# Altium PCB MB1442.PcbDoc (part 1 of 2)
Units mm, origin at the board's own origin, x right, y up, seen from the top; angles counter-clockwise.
Board outline 18.54 x 50.29 mm, 4 copper layers (Top Layer, Signal Layer 1, Signal Layer 2, Bottom Layer); 93 components, 78 nets, 322 pads, 169 vias.
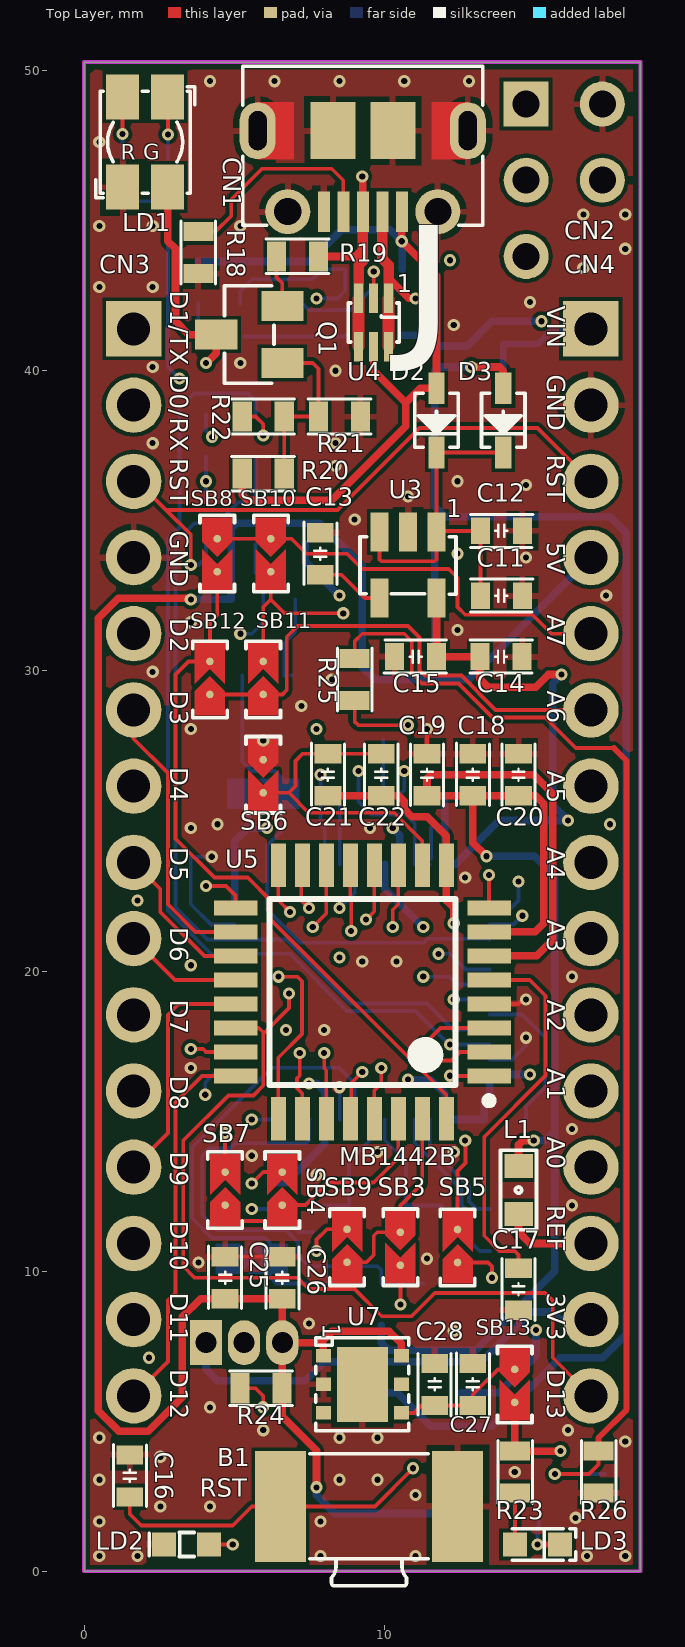
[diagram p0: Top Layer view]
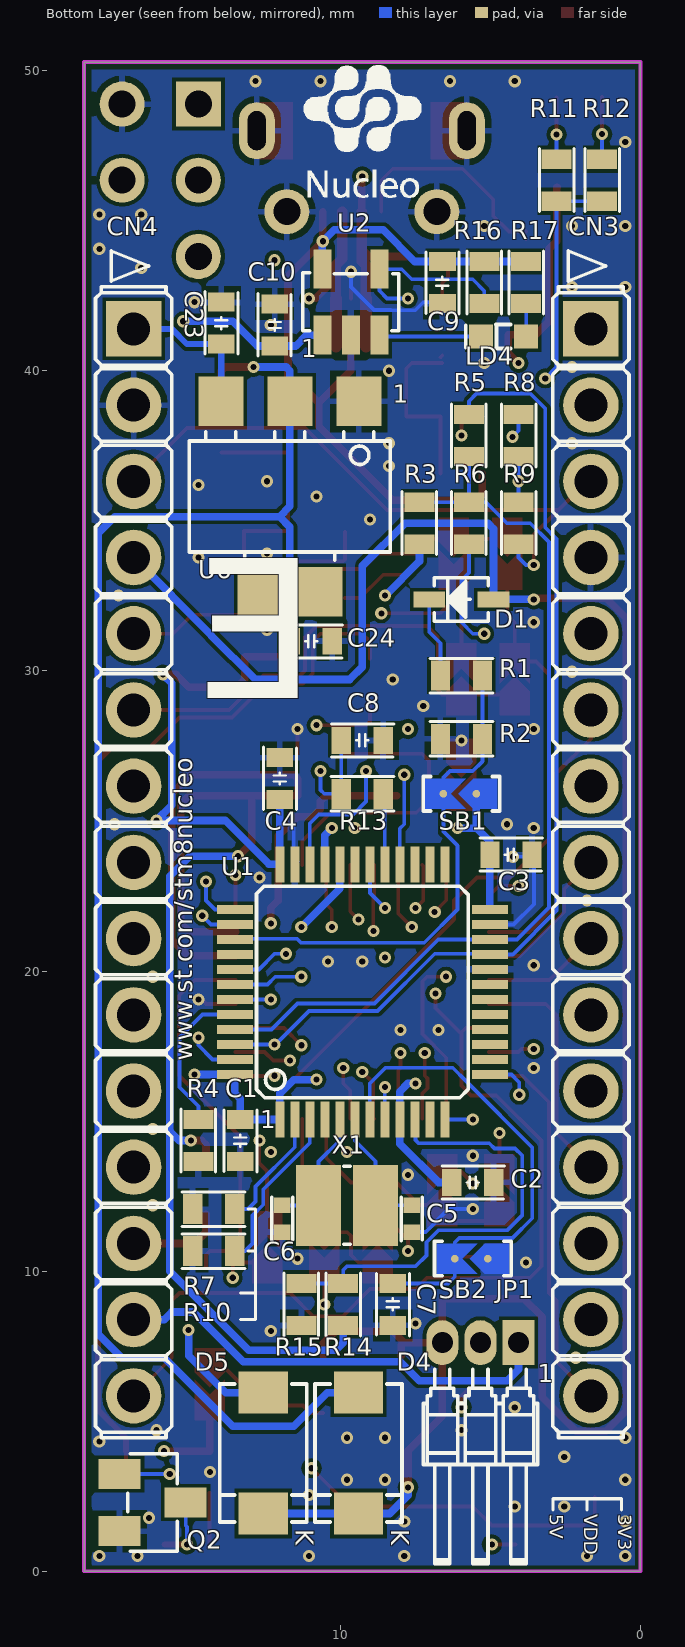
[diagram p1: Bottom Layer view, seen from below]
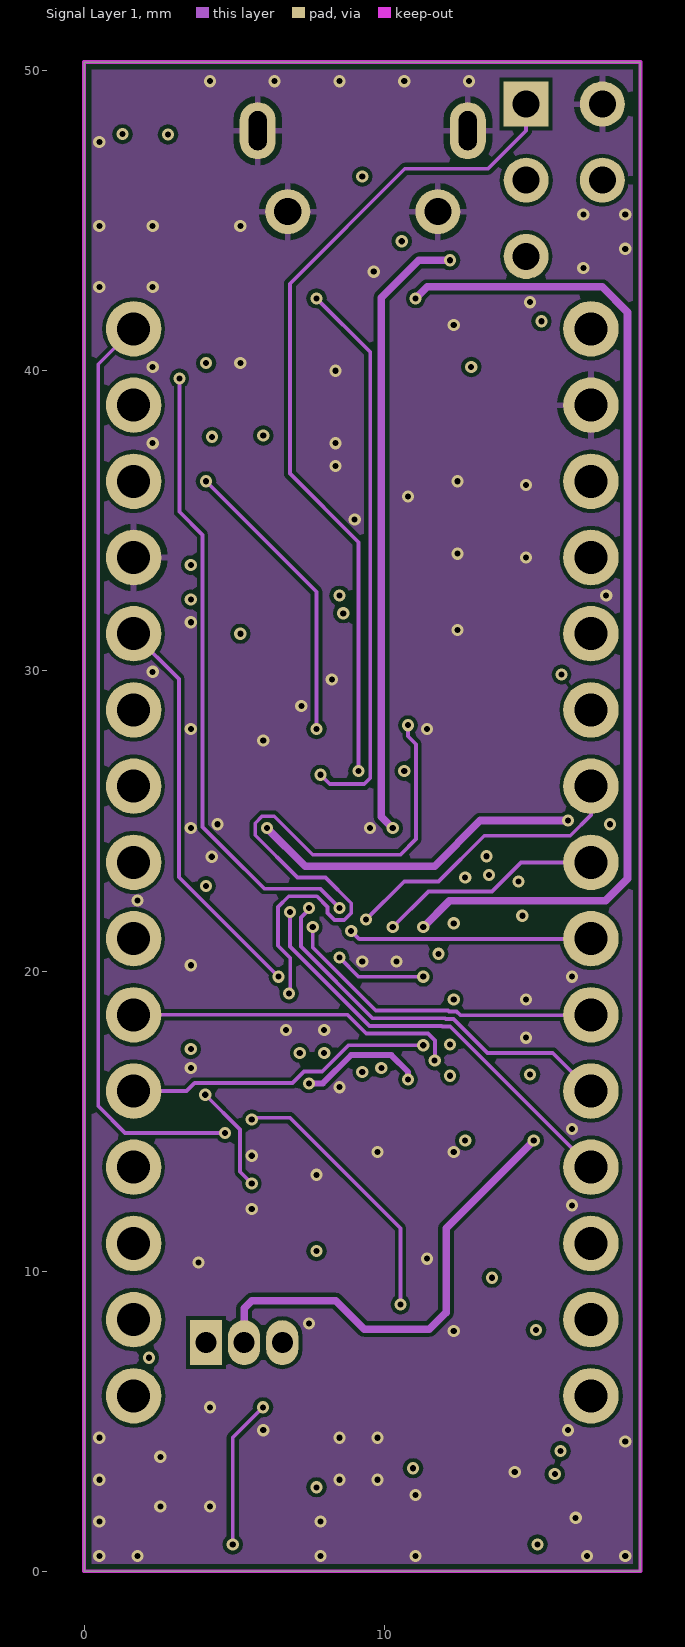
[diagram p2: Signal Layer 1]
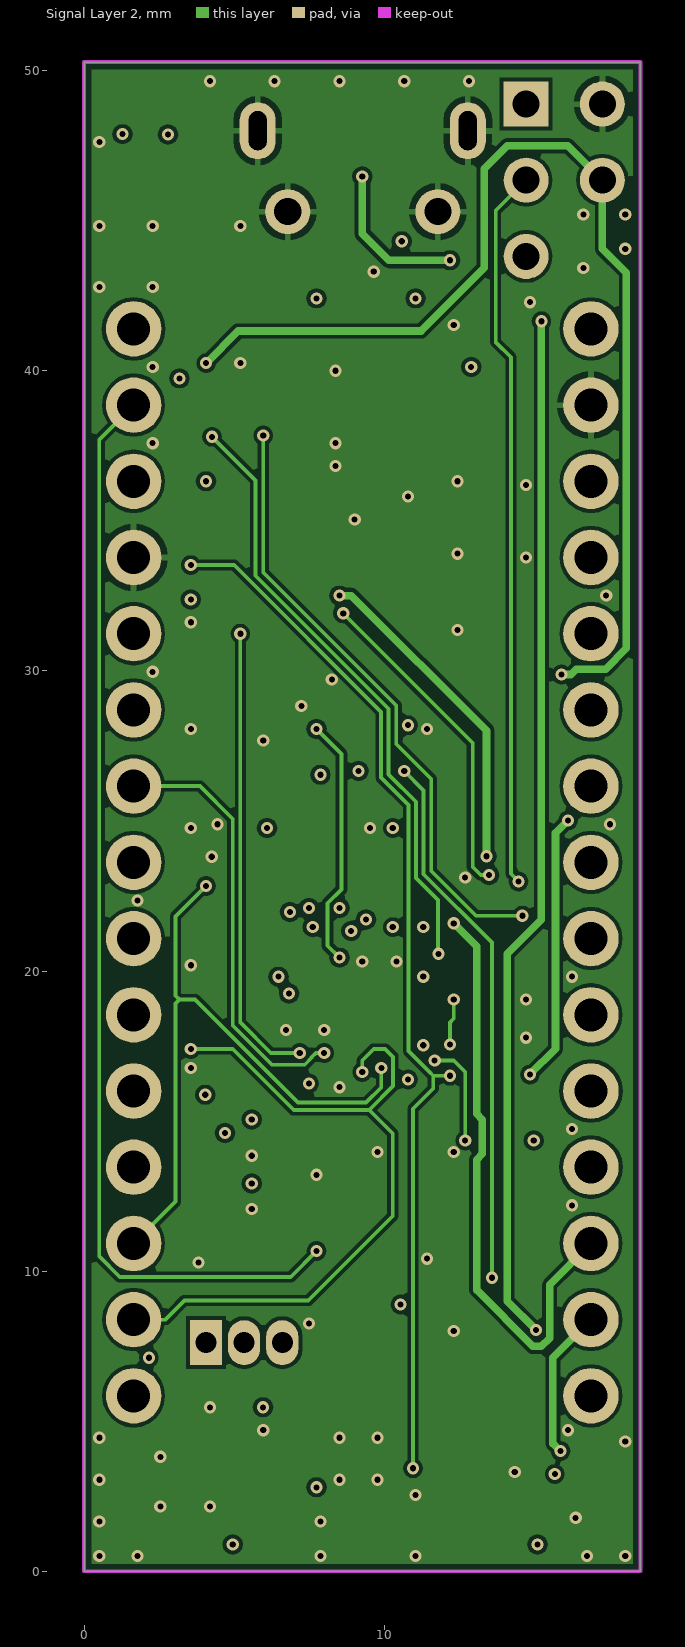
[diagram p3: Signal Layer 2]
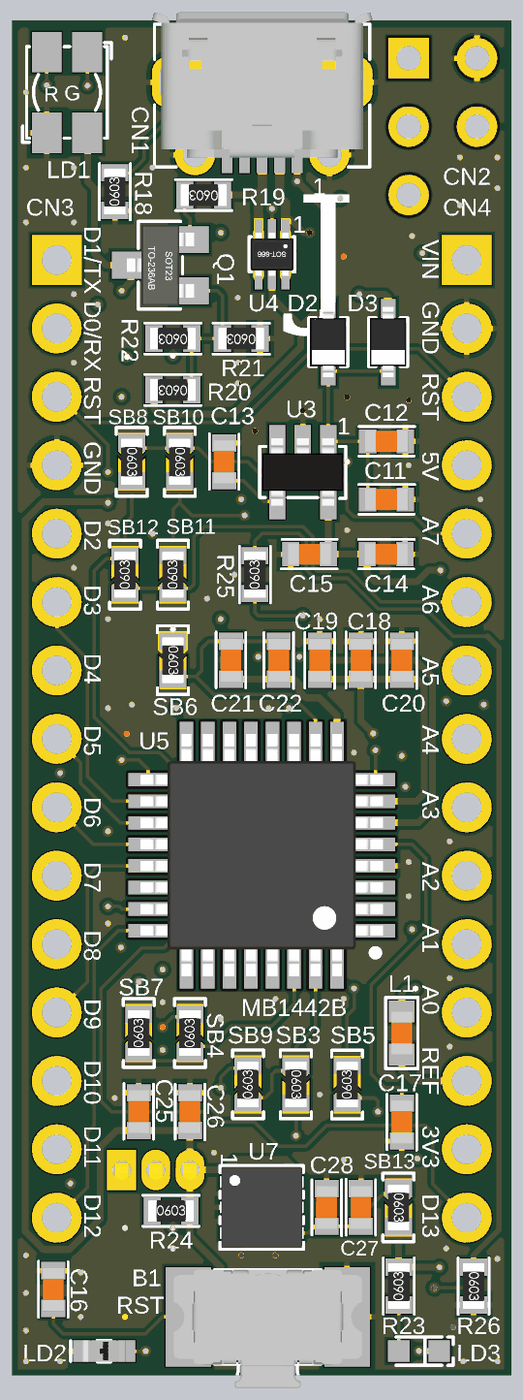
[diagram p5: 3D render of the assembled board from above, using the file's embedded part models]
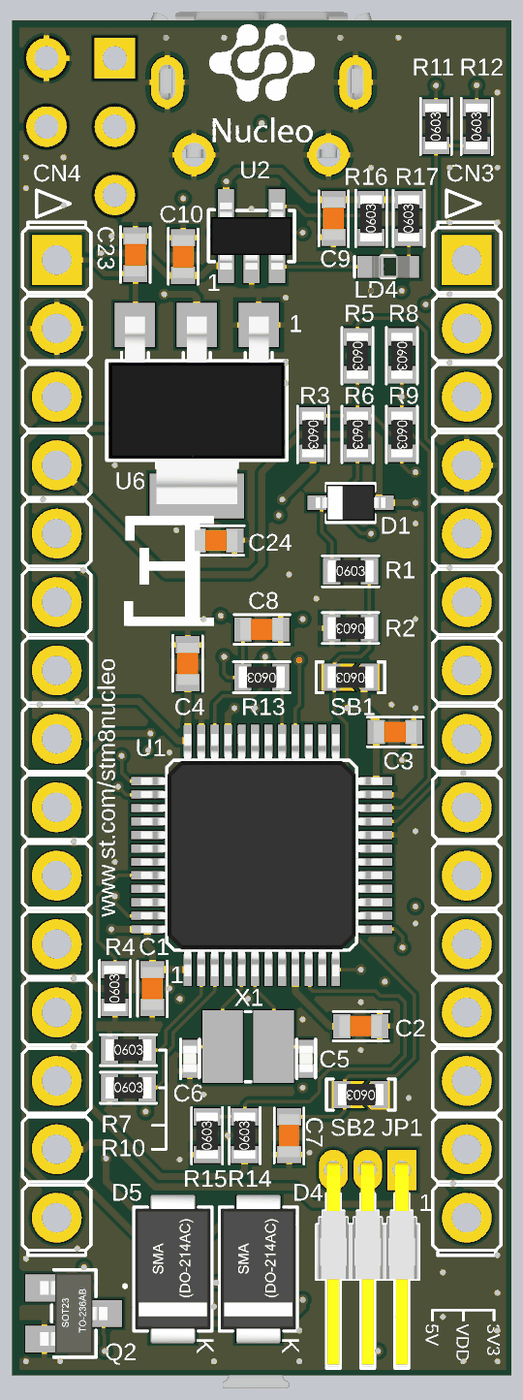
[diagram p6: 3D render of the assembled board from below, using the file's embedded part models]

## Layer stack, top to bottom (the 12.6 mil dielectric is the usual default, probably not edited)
Top Solder: solder mask 0.0102, Solder Resist, Dk 3.5
Top Layer: signal copper 0.0356
Dielectric 1: core 0.32, FR-4, Dk 4.8
Signal Layer 1: signal copper 0.0356
Dielectric 3: prepreg 0.32, FR-4, Dk 4.8
Signal Layer 2: signal copper 0.0356
Dielectric 2: core 0.32, FR-4, Dk 4.8
Bottom Layer: signal copper 0.0356
Bottom Solder: solder mask 0.0102, Solder Resist, Dk 3.5

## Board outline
0,0 0,50.292 18.542,50.292 18.542,0

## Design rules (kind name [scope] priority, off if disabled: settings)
Clearance [All] p1: gap=0.127 ignorepadtopadclearanceinfootprint=FALSE
ComponentClearance [All] p1 off: gap=0.127 collisioncheckmode=3 verticalgap=0.127 showdistances=FALSE
DiffPairsRouting [All] p1: maxlimit=0.254 minlimit=0.254 mostfreqgap=0.254 toplayer_minwidth=0.254 toplayer_maxwidth=0.6 toplayer_prefwidth=0.381 midlayer1_minwidth=0.254 midlayer1_maxwidth=0.6 midlayer1_prefwidth=0.381 midlayer2_minwidth=0.254 midlayer2_maxwidth=0.6 midlayer2_prefwidth=0.381 bottomlayer_minwidth=0.254 bottomlayer_maxwidth=0.6 bottomlayer_prefwidth=0.381 maxuncoupledlength=12.7
HoleSize [All] p1: absolutevalues=TRUE maxlimit=10 minlimit=0.025 maxpercent=80.000 minpercent=20.000
MinimumSolderMaskSliver [All] p1: minsoldermaskwidth=0.04
PlaneClearance [All] p1: clearance=0.254
PlaneConnect [All] p1: planeconnectstyle=Relief reliefexpansion=0.508 reliefentries=4 reliefconductorwidth=0.21 reliefairgap=0.21
PolygonConnect PolygonConnect_via [IsVia] p1: connectstyle=Direct reliefconductorwidth=0.254 reliefentries=4 polygonreliefangle="90 Angle" airgapwidth=0.254
PolygonConnect [All] p2: connectstyle=Relief reliefconductorwidth=0.2 reliefentries=4 polygonreliefangle="90 Angle" airgapwidth=0.2
RoutingVias [All] p1: holewidth=0.3 width=0.8 viastyle="Through Hole" minholewidth=0.3 minwidth=0.8 maxholewidth=0.3 maxwidth=0.8
SilkToSilkClearance [All] p1: silktosilkclearance=0.051
SilkToSolderMaskClearance [IsPad] p1: minsilkscreentomaskgap=0.051 clearancetoexposedcopper=TRUE
SolderMaskExpansion [All] p1: expansion=0.102
Width [All] p1: maxlimit=1 minlimit=0.127 preferedwidth=0.127 midlayer1_maxwidth=0.512 midlayer2_maxwidth=0.512 minimp=50.000000 maximp=50.000000 favimp=50.000000
22 further rules are at their usual default settings.

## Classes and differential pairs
component class U_ST-LinkV2-1_SWIM: C1 C2 C3 C4 C5 C6 C7 C8 C9 C10 C11 C12 C13 C14 C15 CN1 CN2 D1 D2 D3 LD1 LD4 Q1 R1 R2 R3 R4 R5 R6 R7 R8 R9 R10 R11 R12 R13 R14 R15 R16 R17 R18 R19 R20 R21 R22 SB1 SB2 SB3 SB4 U1 U2 U3 U4 X1
component class U_MCU_Power_IOs_Arduino: B1 C16 C17 C18 C19 C20 C21 C22 C23 C24 C25 C26 C27 C28 CN3 CN4 D4 D5 JP1 L1 LD2 LD3 Q2 R23 R24 R25 R26 SB5 SB6 SB7 SB8 SB9 SB10 SB11 SB12 SB13 U5 U6 U7
differential pair ST_LINK_USB_D: +ST_LINK_USB_D_P -ST_LINK_USB_D_N

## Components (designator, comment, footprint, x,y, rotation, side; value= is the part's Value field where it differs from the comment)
B1 "SW-PB" SWI_C&K_ITT_KSS221G 9.496,2.159 r0 top value=KSS221GLFS
C1 "Capacitor" C0603 13.335,14.351 r90 bottom value="100nF, 50V"
C2 "Capacitor" C0603 5.588,12.954 r0 bottom value="100nF, 50V"
C3 "Capacitor" C0603 4.318,23.876 r0 bottom value="100nF, 50V"
C4 "Capacitor" C0603 12.021,26.416 r270 bottom value="100nF, 50V"
C5 "Capacitor" C0402 7.62,11.74 r270 bottom value=12pF
C6 "Capacitor" C0402 11.938,11.74 r270 bottom value=12pF
C7 "Capacitor" C0603 8.255,8.89 r90 bottom value="100nF, 50V"
C8 "Capacitor" C0603 9.271,27.686 r0 bottom value=20pF
C9 "Capacitor" C0603 6.601,42.945 r90 bottom value=1uF
C10 "Capacitor" C0603 12.192,41.529 r270 bottom value="100nF, 50V"
C11 "Capacitor" C0603 13.908,32.512 r180 top value=1uF
C12 "Capacitor" C0603 13.908,34.671 r180 top value="100nF, 50V"
C13 "Capacitor" C0603 7.874,33.909 r270 top value="10nF, 50V"
C14 "Capacitor" C0603 13.894,30.48 r180 top value=1uF
C15 "Capacitor" C0603 11.049,30.48 r0 top value="100nF, 50V"
C16 "Capacitor" C0603 1.524,3.175 r270 top value="100nF, 50V"
C17 "Capacitor" C0603 14.478,9.398 r90 top value=2.2uF
C18 "Capacitor" C0603 12.954,26.543 r270 top value=1uF
C19 "Capacitor" C0603 11.427,26.543 r90 top value="100nF, 50V"
C20 "Capacitor" C0603 14.478,26.543 r90 top value="100nF, 50V"
C21 "Capacitor" C0603 8.125,26.543 r270 top value=1uF
C22 "Capacitor" C0603 9.903,26.543 r90 top value="100nF, 50V"
C23 "Capacitor" C0603 13.97,41.594 r270 bottom value=10uF
C24 "Capacitor" C0603 10.973,30.988 r0 bottom value=10uF
C25 "Capacitor" C0603 4.699,9.779 r270 top value=1uF
C26 "Capacitor" C0603 6.604,9.779 r90 top value="100nF, 50V"
C27 "Capacitor" C0603 12.954,6.223 r270 top value=1uF
C28 "Capacitor" C0603 11.684,6.223 r90 top value="100nF, 50V"
CN1 "USB_uB_105017.0001" CON_USBMICROB_MOLEX_105017-0001_H2P90 9.287,49.456 r180 top value=USB_uB_105017-0001
CN2 "Header STLINK" HDR_1x5_2R54_V_M 14.732,48.895 r270 top
CN3 "Header 15x1" CON_LYCN_313115S161145 1.651,23.622 r270 bottom value="Header 15X1"
CN4 "Header 15x1" CON_LYCN_313115S161145 16.891,23.622 r270 bottom value="Header 15X1"
D1 "BAT60JFILM" DIO_SOD323 5.969,32.385 r0 bottom
D2 "BAT60JFILM" DIO_SOD323 11.745,38.354 r270 top
D3 "BAT60JFILM" DIO_SOD323 13.97,38.354 r270 top
D4 "STPS1L40M" DIO_SMA_1A_2K 9.398,3.937 r90 bottom value=STPS1L30A
D5 "STPS1L40M" DIO_SMA_1A_2K 12.573,3.937 r90 bottom value=STPS1L30A
JP1 "Jumper_Header 3x1" CON_SAMTEC_TMS-103-03-L-S-RA 5.334,4.826 r180 bottom value="Header 3x1"
L1 "BEAD" L0603 14.478,12.7 r90 top value=600R@100MHz
LD1 "LD_BICOLOR_CMS" LED_BI-GR_HSMF-A201-A00J1 2.032,47.625 r0 top
LD2 "LED_red" LED_0603_RED_H0P4 3.417,0.889 r180 top value=RED
LD3 "LED_green" LED_0603_VISHAY_VLMTG1300-GS08_GREEN_1A2K_H0P8 15.113,0.889 r0 top value="TRUE GREEN"
LD4 "LED_red" LED_0603_RED_H0P4 4.572,41.148 r0 bottom value=RED
Q1 "9013-SOT23" NPN_SOT23 5.504,41.209 r90 top value=MMBT2222ALT1G
Q2 "9013-SOT23" NPN_SOT23 16.256,2.286 r270 bottom value=MMBT2222ALT1G
R1 "Resistor" R0603 5.969,29.845 r180 bottom value=2K7
R2 "Resistor" R0603 5.969,27.734 r0 bottom value=4K7
R3 "Resistor" R0603 7.366,34.925 r270 bottom value=680R
R4 "Resistor" R0603 14.732,14.351 r90 bottom value=100K
R5 "Resistor" R0603 5.715,37.846 r270 bottom value=220R
R6 "Resistor" R0603 5.715,34.925 r270 bottom value=47R
R7 "Resistor" R0603 14.224,12.065 r180 bottom value=10K
R8 "Resistor" R0603 4.064,37.846 r270 bottom value=220R
R9 "Resistor" R0603 4.064,34.925 r270 bottom value=47R
R10 "Resistor" R0603 14.224,10.668 r180 bottom value=10K
R11 "Resistor" R0603 2.794,46.355 r90 bottom value=330R
R12 "Resistor" R0603 1.282,46.355 r90 bottom value=330R
R13 "Resistor" R0603 9.271,25.908 r0 bottom value=100R
R14 "Resistor" R0603 9.906,8.89 r90 bottom value=4K7
R15 "Resistor" R0603 11.303,8.89 r90 bottom value=4K7
R16 "Resistor" R0603 5.204,42.948 r90 bottom value=10K
R17 "Resistor" R0603 3.807,42.945 r90 bottom value=1K
R18 "Resistor" R0603 3.81,43.942 r90 top value=100K
R19 "Resistor" R0603 7.112,43.815 r180 top value=1K5
R20 "Resistor" R0603 5.969,36.576 r180 top value=10K
R21 "Resistor" R0603 8.509,38.481 r180 top value=36K
R22 "Resistor" R0603 5.969,38.481 r180 top value=100R
R23 "Resistor" R0603 14.363,3.302 r90 top value=510R
R24 "Resistor" R0603 5.9,6.096 r0 top value=1K
R25 "Resistor" R0603 9.017,29.718 r90 top value=47K
R26 "Resistor" R0603 17.145,3.302 r270 top value=100K
SB1 "SB_OFF" SOLDER-BRIDGE_R0603-0R 5.969,25.908 r0 bottom
SB2 "SB_OFF" SOLDER-BRIDGE_R0603-0R 5.588,10.414 r0 bottom
SB3 "SB_ON" SOLDER-BRIDGE_R0603-0R 10.541,10.795 r270 top
SB4 "SB_ON" SOLDER-BRIDGE_R0603-0R 6.604,12.7 r90 top
SB5 "SB_OFF" SOLDER-BRIDGE_R0603-0R 12.446,10.787 r90 top
SB6 "SB_ON" SOLDER-BRIDGE_R0603-0R 5.969,26.543 r270 top
SB7 "SB_OFF" SOLDER-BRIDGE_R0603-0R 4.699,12.7 r90 top
SB8 "SB_ON" SOLDER-BRIDGE_R0603-0R 4.438,33.909 r270 top
SB9 "SB_OFF" SOLDER-BRIDGE_R0603-0R 8.763,10.795 r90 top
SB10 "SB_OFF" SOLDER-BRIDGE_R0603-0R 6.223,33.909 r270 top
SB11 "SB_ON" SOLDER-BRIDGE_R0603-0R 5.969,29.718 r90 top
SB12 "SB_OFF" SOLDER-BRIDGE_R0603-0R 4.191,29.718 r90 top
SB13 "SB_ON" SOLDER-BRIDGE_R0603-0R 14.351,6.223 r270 top
U1 "STM32F103CBT6" ICC_LQFP48_7X7_P050 9.271,19.304 r180 bottom
U2 "STMPS2141STR" MOS_SOT23-5L 9.652,42.291 r180 bottom
U3 "LD3985M33R" REG_SOT23-5L 10.795,33.528 r180 top
U4 "USBLC6-2P6" ESD_SOT666 9.652,41.613 r180 top
U5 "STM8S207K8T6" TQFP80P900X900X160-32N 9.271,19.304 r180 top value=STM8S207K8T6C
U6 "LD1117S50TR" REG_SOT223-TAB 11.684,35.814 r0 bottom
U7 "LD39050PU33R" ICC_DFN6-EPAD_3X3_P095 9.271,6.223 r270 top
X1 "XTAL_2_PINS" CRY_NX3225GD_2P 9.779,12.192 r180 bottom value="NX3225GD 8MHz"

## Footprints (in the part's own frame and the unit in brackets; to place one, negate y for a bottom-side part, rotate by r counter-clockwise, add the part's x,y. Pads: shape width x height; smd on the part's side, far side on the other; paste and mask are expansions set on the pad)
C0402 [mm]
  rect 0.51x0.56 smd mask+0.05: 1(-0.45,0) 2(0.45,0)
  silkscreen extent -0.72,-0.35 0.72,0.35, body extent -0.5,-0.3 0.5,0.3, height 0.4
C0603 [mm]
  rect 0.64x0.89 smd mask+0.05: 1(-0.7,0) 2(0.7,0)
  silkscreen extent -1.05,-0.55 1.02,0.55, body extent -0.9,-0.5 0.9,0.5, height 1.4
CON_LYCN_313115S161145 [mm]
  rect 1.85x1.85 / inner round 1.85 / far side rect 1.85x1.85 hole 1.1 mask+0.05: 1(-17.78,0)
  round 1.85 hole 1.1 mask+0.05: 2(-15.24,0) 3(-12.7,0) 4(-10.16,0) 5(-7.62,0) 6(-5.08,0) 7(-2.54,0) 8(0,0) 9(2.54,0) 10(5.08,0) 11(7.62,0) 12(10.16,0) 13(12.7,0) 14(15.24,0) 15(17.78,0)
  silkscreen extent -20.38,-1.27 19.18,1.27, body extent -19.18,-1.27 19.18,1.27, height 8.5
CON_SAMTEC_TMS-103-03-L-S-RA [mm] "MCD-01484"
  rect 1.07x1.5 hole 0.7 mask+0.05: 1(1.27,2.79)
  oval 1.07x1.5 hole 0.7 mask+0.05: 2(0,2.79) 3(-1.27,2.79)
  silkscreen extent -1.91,-4.57 1.91,1.91, body extent -1.91,-4.44 1.91,3.05, height 2.48
CON_USBMICROB_MOLEX_105017-0001_H2P90 [mm]
  rect 0.4x1.35 smd mask+0.05: 1(-1.3,4.15) 2(-0.65,4.15) 3(0,4.15) 4(0.65,4.15) 5(1.3,4.15)
  round 1.5 hole 0.9 mask+0.05: 6(-2.5,4.15) 7(2.5,4.15)
  oval 1.2x1.9 hole 0.6 slot 1.3 at 90 deg mask+0.05: 8(3.5,1.45) 9(-3.5,1.45)
  rect 1.5x1.9 smd mask+0.05: 10(-1,1.45) 11(1,1.45)
  Top Layer region: 2.3,2.4 3.5,2.4 3.5,0.5 2.3,0.5 2.3,2.4
  Top Layer region: -3.5,2.4 -2.3,2.4 -2.3,0.5 -3.5,0.5 -3.5,2.4
  silkscreen extent -4,-0.7 4,4.6, body extent -4.1,-1.15 4.1,4.66, height 2.9
CRY_NX3225GD_2P [mm]
  rect 1.5x2.7 smd mask+0.05: 1(-0.95,0) 2(0.95,0)
  silkscreen extent -0.1,-1.3 0.1,1.3, body extent -1.65,-1.3 1.65,1.3, height 1
DIO_SMA_1A_2K [mm]
  rect 1.4x1.64 smd mask+0.05: 1(2.015,0) 2(-2.015,0)
  silkscreen extent -2.3,-1.45 2.3,1.45, body extent -2.75,-1.45 2.75,1.45, height 2.7
DIO_SOD323 [mm]
  rect 1.06x0.54 smd mask+0.05: 1(-1.07,0) 2(1.07,0)
  silkscreen extent -0.9,-0.72 0.9,0.72, body extent -1.3,-0.78 1.3,0.78, height 1.17
ESD_SOT666 [mm]
  rect 0.3x0.99 smd mask+0.05: 1(-0.5,-0.805) 2(0,-0.805) 3(0.5,-0.805) 4(0.5,0.805) 5(0,0.805) 6(-0.5,0.805)
  silkscreen extent -0.85,-0.65 0.85,0.65, body extent -0.85,-0.8 0.85,0.8, height 0.6
HDR_1x5_2R54_V_M [mm] "Header IDC, 2 x 4 Pin Vertical 2.54mm Pitch (Non-Boxed, Male)"
  rect 1.5x1.5 hole 0.9: 1(0,0)
  round 1.5 hole 0.9: 2(0,2.54) 3(2.54,0) 4(2.54,2.54) 5(5.08,0)
ICC_DFN6-EPAD_3X3_P095 [mm]
  rect 0.45x0.5 smd mask+0.05: 1(-0.95,-1.3) 2(0,-1.3) 3(0.95,-1.3) 4(0.95,1.3) 5(0,1.3) 6(-0.95,1.3)
  rect 2.5x1.7 smd mask+0.05: EP(0,0)
  silkscreen extent -1.55,-1.55 1.55,1.55, body extent -1.55,-1.55 1.55,1.55, height 1
ICC_LQFP48_7X7_P050 [mm]
  rect 0.3x1.2 smd mask+0.05: 1(-2.75,-4.25) 2(-2.25,-4.25) 3(-1.75,-4.25) 4(-1.25,-4.25) 5(-0.75,-4.25) 6(-0.25,-4.25) 7(0.25,-4.25) 8(0.75,-4.25) 9(1.25,-4.25) 10(1.75,-4.25) 11(2.25,-4.25) 12(2.75,-4.25) 25(2.75,4.25) 26(2.25,4.25) 27(1.75,4.25) 28(1.25,4.25) 29(0.75,4.25) 30(0.25,4.25) 31(-0.25,4.25) 32(-0.75,4.25) 33(-1.25,4.25) 34(-1.75,4.25) 35(-2.25,4.25) 36(-2.75,4.25)
  rect 1.2x0.3 smd mask+0.05: 13(4.25,-2.75) 14(4.25,-2.25) 15(4.25,-1.75) 16(4.25,-1.25) 17(4.25,-0.75) 18(4.25,-0.25) 19(4.25,0.25) 20(4.25,0.75) 21(4.25,1.25) 22(4.25,1.75) 23(4.25,2.25) 24(4.25,2.75) 37(-4.25,2.75) 38(-4.25,2.25) 39(-4.25,1.75) 40(-4.25,1.25) 41(-4.25,0.75) 42(-4.25,0.25) 43(-4.25,-0.25) 44(-4.25,-0.75) 45(-4.25,-1.25) 46(-4.25,-1.75) 47(-4.25,-2.25) 48(-4.25,-2.75)
  silkscreen extent -3.52,-3.52 3.52,3.52, body extent -4.5,-4.5 4.5,4.5, height 1.6
L0603 [mm]
  rect 0.8x0.95 smd mask+0.05: 1(-0.8,0) 2(0.8,0)
  silkscreen extent -1.33,-0.6 1.33,0.6, body extent -0.87,-0.47 0.87,0.47, height 0.95
LED_0603_RED_H0P4 [mm]
  rect 0.8x0.8 smd mask+0.05: 1(-0.75,0) 2(0.75,0)
  silkscreen extent -0.25,-0.4 1.25,0.4, body extent -0.8,-0.4 0.79,0.4, height 0.4
LED_0603_VISHAY_VLMTG1300-GS08_GREEN_1A2K_H0P8 [mm]
  rect 0.8x0.8 smd mask+0.05: 1(-0.75,0) 2(0.75,0)
  silkscreen extent -0.85,-0.53 1.28,0.53, body extent -0.85,-0.45 0.85,0.45, height 0.8
LED_BI-GR_HSMF-A201-A00J1 [mm]
  rect 1.1x1.5 smd mask+0.05: 1(-0.75,-1.5) 2(-0.75,1.5) 3(0.75,1.5) 4(0.75,-1.5)
  silkscreen extent -1.65,-1.85 1.65,1.85, body extent -1.5,-1.85 1.5,1.85, height 2.1
MOS_SOT23-5L [mm]
  rect 0.6x1.3 smd mask+0.05: 1(-0.95,-1.1) 2(0,-1.1) 3(0.95,-1.1) 4(0.95,1.1) 5(-0.95,1.1)
  silkscreen extent -1.6,-0.95 1.6,0.97, body extent -1.52,-1.25 1.52,1.25, height 1.45
NPN_SOT23 [mm]
  rect 1x1.4 smd mask+0.05: 1(-0.95,-1.1) 2(0.95,-1.1) 3(0,1.1)
  silkscreen extent -1.63,-0.82 1.63,0.82, body extent -1.56,-1.25 1.56,1.25, height 1.1
R0603 [mm]
  rect 0.64x1 smd mask+0.05: 1(-0.7,0) 2(0.7,0)
  silkscreen extent -1.05,-0.58 1.05,0.58, body extent -0.9,-0.5 0.9,0.5, height 0.56
REG_SOT23-5L [mm]
  rect 0.6x1.3 smd mask+0.05: 1(-0.95,-1.1) 2(0,-1.1) 3(0.95,-1.1) 4(0.95,1.1) 5(-0.95,1.1)
  silkscreen extent -1.6,-0.95 1.6,0.97, body extent -1.52,-1.25 1.52,1.25, height 1.1
REG_SOT223-TAB [mm]
  rect 1.5x1.65 smd mask+0.05: 1(-2.3,-3.175) 2(0,-3.175) 3(2.3,-3.175)
  rect 3.5x1.65 smd mask+0.05: 4(0,3.175)
  silkscreen extent -3.35,-2.15 3.35,2.12, body extent -3.35,-3.48 3.35,3.48, height 1.8
SOLDER-BRIDGE_R0603-0R [mil]
  round 10 smd paste-393.7: 1(-19.68,0) 2(23.62,0)
  Top Layer region: -5.91,19.68 13.78,0 -5.91,-19.69 47.24,-19.69 47.24,19.68 -5.91,19.68
  Top Layer region: -47.24,-19.69 -47.24,19.68 -15.75,19.68 3.94,0 -15.75,-19.69 -47.24,-19.69
  silkscreen extent -50,-23 50,23, body extent -36,-20 36,20, height 22
SWI_C&K_ITT_KSS221G [mm] "MCD-01335"
  rect 1.7x3.7 smd mask+0.05: 1(-2.95,0) 2(2.95,0)
  silkscreen extent -1.97,-2.65 1.97,1.75, body extent -3.5,-2.65 3.5,1.76, height 1.7
TQFP80P900X900X160-32N [mm] "TQFP, 32-Leads, Body 7,00x7,00mm, Pitch 0,80mm, IPC Medium Density"
  rect 1.45x0.5 smd: 1(-4.225,2.8) 2(-4.225,2) 3(-4.225,1.2) 4(-4.225,0.4) 5(-4.225,-0.4) 6(-4.225,-1.2) 7(-4.225,-2) 8(-4.225,-2.8) 17(4.225,-2.8) 18(4.225,-2) 19(4.225,-1.2) 20(4.225,-0.4) 21(4.225,0.4) 22(4.225,1.2) 23(4.225,2) 24(4.225,2.8)
  rect 0.5x1.45 smd: 9(-2.8,-4.225) 10(-2,-4.225) 11(-1.2,-4.225) 12(-0.4,-4.225) 13(0.4,-4.225) 14(1.2,-4.225) 15(2,-4.225) 16(2.8,-4.225) 25(2.8,4.225) 26(2,4.225) 27(1.2,4.225) 28(0.4,4.225) 29(-0.4,4.225) 30(-1.2,4.225) 31(-2,4.225) 32(-2.8,4.225)
  silkscreen extent -4.35,-3.1 3.1,3.75, body extent -4.5,-4.5 4.5,4.5, height 1.6

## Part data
B1: library part MCD-01335, "Subminiature Side Actuated Tact Switch for SMT - KSS series - 2.0 Newtons - Gull wing, SPST", Manufacturer=C&K, Manufacturer_Part_Number=KSS221GLFS
C1 C2 C3 C4 C7 C10 C12 C15 C16 C19 C20 C22 C26 C28: library part MCD-01099, "Capacitor,100nF,50V,X7R,10%,0603", Manufacturer=YAGEO, Manufacturer_Part_Number=CC0603KRX7R9BB104, Package=C0603
C5 C6: library part MCD-00200, "Capacitor, MLCC, 12pF, 50V, NPO, 5%, 0402, T=0,5mm", Manufacturer=YAGEO, Manufacturer_Part_Number=CC0402JRNPO9BN120, Package=C0402
C8: library part MCD-00638, "Capacitor, MLCC, 20pF, 50V, NPO, 5%, 0603, T=0,8mm", Manufacturer=YAGEO, Manufacturer_Part_Number=CC0603JRNPO9BN200, Package=C0603
C9 C11 C14 C18 C21 C25 C27: library part MCD-01053, "Capacitor, C-series, X5R, 1µF, 50V, 10%, 0603, T=0.8mm", Manufacturer=TDK, Manufacturer_Part_Number=C1608X5R1H105K080AB, Package=C0603
C13: library part MCD-01102, "Capacitor,10nF,50V,X7R,10%,0603", Manufacturer=YAGEO, Manufacturer_Part_Number=CC0603KRX7R9BB103, Package=C0603
C17: library part MCD-00654, "Capacitor,2.2uF,16V, X5R,10%,0603,YAGEO", Manufacturer=YAGEO, Manufacturer_Part_Number=CC0603KRX5R7BB225, Package=C0603
C23 C24: library part MCD-01124, "Capacitor, MLCC, 10µF, 10V, X5R, 10%, 0603, T=0.8mm", Manufacturer=MURATA, Manufacturer_Part_Number=GRM188R61A106KAAL, Package=C0603
CN1: library part MCD-00028, "USB-MICRO-B, 0.65mm, RA, SMT, Bottom Mount,", Manufacturer=MOLEX, Manufacturer_Part_Number=1050170001
CN2: library part MCD-01399, "Header 5 pads for ST-LINK prog. Not fitted", Manufacturer=n/a
CN3 CN4: library part MCD-01332, "Pin header, 15x1, 2,54mm, VR, TH, Height 6mm/6mm", Alternate_Manufacturer=SAMTEC, Alternate_Manufacturer_Part_Number="TSW 115-08-F-S", Manufacturer=LYCONN, Manufacturer_Part_Number=313115S161145
D1 D2 D3: library part MCD-00034, Manufacturer=STMICROELECTRONICS
D4 D5: library part MCD-01059, "LOW DROP POWER SCHOTTKY RECTIFIER 1A 30V VF=0.3V", Manufacturer=STMICROELECTRONICS, Manufacturer_Part_Number=STPS1L30A, Package=DIO_SMA_1A_2K
JP1: library part MCD-01484, "Header 3x1, 1.27mm, RA,SMT, Height 3.18mm", Manufacturer=SAMTEC, Manufacturer_Part_Number=TMS-103-03-L-S-RA
L1: library part MCD-00047, "SMD Chip ferrite bead, 600R@100MHz +/-25%, 350mA, 500mohm DC, 0603, T=0.8mm", Manufacturer=TAI-TECH, Manufacturer_Part_Number=FCM1608KF-601T03
LD1: library part MCD-00051, "LED Bicolor", Alternate_Manufacturer=EVERLUCK, Alternate_Manufacturer_Part_Number=LE-RGW35280, Manufacturer="AVAGO TECHNOLOGIES", Manufacturer_Part_Number=HSMF-A201-A00J1
LD2 LD4: library part MCD-00322, "LED, Red, 0603", Manufacturer=EVERLIGHT, Manufacturer_Part_Number=19-217/R6C-AL1M2VY/3T, Package="LED 0603"
LD3: library part MCD-00589, "LED Green, 0603 SMD, Fw Voltage = 2.8V - 3.6V", Alternate_Manufacturer="OSRAM OPTO SEMICONDUCTORS", Alternate_Manufacturer_Part_Number="LG Q396-PS-35", Manufacturer=VISHAY, Manufacturer_Part_Number=VLMTG1300-GS08, Package="LED 0603"
Q1 Q2: library part MCD-01737, "NPN Bipolar Transistor", Manufacturer="ON SEMICONDUCTOR", Manufacturer_Part_Number=MMBT2222ALT1G
R1: library part MCD-00218, "Resistor,2K7,0603,1%,1/10W", Manufacturer=YAGEO, Manufacturer_Part_Number=RC0603FR-072K7L, Package=R0603
R2 R14 R15: library part MCD-00219, "Resistor,4K7,0603,1%,1/10W", Manufacturer=YAGEO, Manufacturer_Part_Number=RC0603FR-074K7L, Package=R0603
R3: library part MCD-00508, "Resistor,680R,0603,1%,1/10W", Manufacturer=YAGEO, Manufacturer_Part_Number=RC0603FR-07680RL, Package=R0603
R4 R18 R26: library part MCD-00223, "Resistor,100K,0603,1%,1/10W", Manufacturer=YAGEO, Manufacturer_Part_Number=RC0603FR-07100KL, Package=R0603
R5 R8: library part MCD-00428, "Resistor,220R,0603,1%,1/10W", Manufacturer=YAGEO, Manufacturer_Part_Number=RC0603FR-07220RL, Package=R0603
R6 R9: library part MCD-00482, "Resistor,47R,0603,1%,1/10W", Manufacturer=YAGEO, Manufacturer_Part_Number=RC0603FR-0747RL, Package=R0603
R7 R10 R16 R20: library part MCD-00220, "Resistor,10K,0603,1%,1/10W", Manufacturer=YAGEO, Manufacturer_Part_Number=RC0603FR-0710KL, Package=R0603
R11 R12: library part MCD-00197, "Resistor,330R,0603,1%,1/10W", Manufacturer=YAGEO, Manufacturer_Part_Number=RC0603FR-07330RL, Package=R0603
R13 R22: library part MCD-00224, "Resistor,100R,0603,1%,1/10W", Manufacturer=YAGEO, Manufacturer_Part_Number=RC0603FR-07100RL, Package=R0603
R17 R24: library part MCD-00070, "Resistor,1K,0603,1%,1/10W", Manufacturer=YAGEO, Manufacturer_Part_Number=RC0603FR-071KL, Package=R0603
R19: library part MCD-00217, "Resistor,1K5,0603,1%,1/10W", Manufacturer=YAGEO, Manufacturer_Part_Number=RC0603FR-071K5L, Package=R0603
R21: library part MCD-00221, "Resistor,36K,0603,1%,1/10W", Manufacturer=YAGEO, Manufacturer_Part_Number=RC0603FR-0736KL, Package=R0603
R23: library part MCD-00225, "Resistor,510R,0603,1%,1/10W", Manufacturer=YAGEO, Manufacturer_Part_Number=RC0603FR-07510RL, Package=R0603
R25: library part MCD-00222, "Resistor,47K,0603,1%,1/10W", Manufacturer=YAGEO, Manufacturer_Part_Number=RC0603FR-0747KL, Package=R0603
SB1 SB2 SB5 SB7 SB9 SB10 SB12: library part MCD-00072, "Solder Bridge OFF", Manufacturer=YAGEO, Manufacturer_Part_Number=RC0603JR-070RL, Package=SB0603
SB3 SB4 SB6 SB8 SB11 SB13: library part MCD-00071, "Solder Bridge ON", Manufacturer=YAGEO, Manufacturer_Part_Number=RC0603JR-070RL, Package=SB0603
U1: library part MCD-00085, "Medium-density performance line ARM-based 32-bit MCU with 128KB Flash", Manufacturer=STMICROELECTRONICS
U2: library part MCD-00083, "Enhanced single channel power switches with active low enable pin", Alternate_Manufacturer="TEXAS INSTRUMENTS", Alternate_Manufacturer_Part_Number=TPS2041C, Manufacturer=STMICROELECTRONICS
U3: library part MCD-00086, "Ultra low drop-low noise BiCMOS voltage, regulators low ESR capacitors compatible", Manufacturer=STMICROELECTRONICS
U4: library part MCD-00169, "USB OTG FS ESD protection", Manufacturer=STMICROELECTRONICS
U5: library part MCD-01331, "IC, STM8S207K8T6, STM8S 8-bit MCU, 64 KB Flash, Performance line, 24 MHz", Manufacturer=STMICROELECTRONICS, Manufacturer_Part_Number=STM8S207K8T6C, Package=LQFP32
U6: library part MCD-00088, "IC REG LDO 5V 0.8A SOT223", Manufacturer=STMICROELECTRONICS, Package=SOT-223
U7: library part MCD-00215, "Low quiescent current and low noise voltage regulators", Manufacturer=STMICROELECTRONICS, Package="DFN6 3x3mm"
X1: library part MCD-00092, "Crystal 8MHz, 8pF, +-20ppm, 500ohms max,  SMD", Manufacturer=NDK, Manufacturer_Part_Number="NX3225GD 8MHz EXS00A-CG04874"

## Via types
v1: diameter 0.406, hole 0.203, Top Layer to Bottom Layer, tented both sides, 169 vias

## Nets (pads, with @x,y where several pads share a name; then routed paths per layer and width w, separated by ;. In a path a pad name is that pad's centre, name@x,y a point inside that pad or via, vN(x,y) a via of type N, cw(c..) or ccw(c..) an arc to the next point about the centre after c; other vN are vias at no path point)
3V3: CN4.14 JP1.1 R23.2 SB13.2 | length 23.7
  Top Layer w0.254: SB13.2@14.351,5.623 14.351,4.014 R23.2@14.363,4.002 v1(15.875,4.002) ; CN4.14@16.891,7.747 CN4.14@16.891,8.382
  Signal Layer 2 w0.254: v1(15.875,4.002) 15.621,4.256 15.621,7.112 CN4.14@16.891,8.382
  Bottom Layer w0.254: JP1.1@4.064,7.616 4.064,6.731 4.445,6.35 7.366,6.35 8.001,6.985 13.239,6.985 14.89,8.636 15.621,8.636 15.875,8.382 CN4.14@16.891,8.382
3V3_ST_LINK: C1.2 C2.2 C3.2 C4.2 C14.2 C15.2 CN2.4 LD1.4 Q1.3 SB1.1 U1.1 U1.9 U1.24 U1.36 U1.48 U3.5 | length 103.7
  Top Layer w0.254: LD1.4@2.782,46.125 2.794,46.113 2.794,44.323 3.048,44.069 3.048,41.656 3.495,41.209 Q1.3@4.404,41.209 4.404,40.596 v1(4.067,40.259) ; U3.5@11.745,32.428 11.745,30.484 C15.2@11.749,30.48 C14.2@13.194,30.48 13.194,29.732 13.462,29.464 15.056,29.464 15.473,29.881 v1(15.913,29.881)
  Signal Layer 1 w0.203: v1(7.493,16.256) 7.955,16.256 8.895,17.196 10.236,17.196 10.795,16.637 v1(10.795,16.383)
  Signal Layer 1 w0.254: v1(6.096,24.765) 7.366,23.495 11.684,23.495 13.208,25.019 v1(16.129,25.019)
  Signal Layer 2 w0.254: v1(4.067,40.259) 5.141,41.332 11.233,41.332 13.335,43.434 13.335,46.736 14.103,47.504 16.123,47.504 CN2.4@17.272,46.355 17.272,44.069 18.07,43.271 18.07,30.754 17.379,30.063 16.403,30.063 16.221,29.881 v1(15.913,29.881) ; v1(14.859,16.554) 15.712,17.407 15.712,24.602 v1(16.129,25.019)
  Bottom Layer w0.203: C3.2@5.018,23.876 C3.2@5.021,23.873
  Bottom Layer w0.254: C3.2@5.018,23.876 5.018,24.322 5.461,24.765 5.469,24.765 ; U1.24@5.021,22.054 C3.2@5.021,23.873 ; SB1.1@5.469,25.908 5.469,24.765 ; v1(6.096,24.765) 5.469,24.765 ; C2.2@6.288,12.954 6.731,12.954 8.021,14.244 U1.9@8.021,15.054 8.021,15.982 7.747,16.256 v1(7.493,16.256) ; v1(10.795,16.383) 11.557,16.383 12.021,15.919 U1.1@12.021,15.054 12.024,15.051 C1.2@13.335,15.051 13.335,15.748 13.521,15.934 U1.48@13.521,16.554 v1(14.859,16.554) ; C4.2@12.021,25.716 U1.36@12.021,23.554 12.378,23.554 13.843,25.019 v1(16.129,25.019) 15.621,25.527 15.621,29.589 v1(15.913,29.881)
5V: C25.2 C26.1 CN4.4 D1.1 D4.2 D5.2 JP1.3 R24.2 U7.1 U7.6 | length 78.5
  Top Layer w0.254: v1(3.556,32.385) 3.52,32.421 1.143,32.421 0.472,31.75 0.472,5.354 1.163,4.663 2.139,4.663 3.275,5.799 3.275,8.471 3.883,9.079 C25.2@4.699,9.079 C26.1@6.604,9.079 JP1.3@6.604,7.616 ; v1(7.747,2.794) 7.747,4.017 6.604,5.16 6.604,6.092 R24.2@6.6,6.096 6.604,6.1 JP1.3@6.604,7.616 ; U7.1@7.971,7.173 7.971,7.523 7.878,7.616 ; U7.6@10.571,7.173 10.571,7.59 10.16,8.001 8.263,8.001 7.878,7.616 ; JP1.3@6.604,7.616 7.878,7.616
  Bottom Layer w0.254: v1(3.556,32.385) D1.1@4.899,32.385 4.899,34.744 5.08,34.925 7.845,34.925 9.271,33.499 9.271,30.133 9.686,29.718 12.839,29.718 14.3,31.18 14.3,31.191 CN4.4@16.891,33.782 ; v1(7.747,2.794) 7.747,2.525 8.35,1.922 D4.2@9.398,1.922 D5.2@12.573,1.922
5V_ST_LINK: C9.2 CN1.1 D2.1 R16.2 R17.2 R20.2 U2.5 U4.5 | length 26.3
  Top Layer w0.254: R20.2@5.269,36.576 5.269,35.879 5.461,35.687 8.255,35.687 10.719,38.151 10.719,38.938 ; U4.5@9.652,40.808 9.652,40.005 10.719,38.938 ; CN1.1@10.587,45.306 v1(10.587,44.323) 11.745,43.165 D2.1@11.745,39.424 11.204,39.424 10.719,38.938
  Bottom Layer w0.254: R17.2@3.807,43.645 5.201,43.645 R16.2@5.204,43.648 6.598,43.648 C9.2@6.601,43.645 7.52,43.645 8.579,44.704 10.206,44.704 v1(10.587,44.323) 10.602,44.308 U2.5@10.602,43.391
5V_ST_LINK_SW: C10.2 D5.1 U2.1 | length 43.5
  Signal Layer 2 w0.254: v1(15.06,8.039) 14.097,9.002 14.097,20.574 15.24,21.717 v1(15.24,41.656)
  Bottom Layer w0.254: U2.1@10.602,41.191 11.133,41.191 11.495,40.829 C10.2@12.192,40.829 12.762,40.829 13.588,41.655 v1(15.24,41.656) ; D5.1@12.573,5.952 13.826,5.952 15.06,7.186 v1(15.06,8.039) ; v1(15.24,41.656) v1(15.24,41.656)
5V_VIN: C24.2 D3.1 D4.1 U6.2 U6.4 | length 55.7
  Top Layer w0.254: v1(12.9,40.132) 13.843,40.132 13.97,40.005 D3.1@13.97,39.424
  Bottom Layer w0.254: D4.1@9.398,5.952 10.431,5.952 11.557,4.826 13.589,4.826 15.875,7.112 17.288,7.112 18.07,7.894 18.07,34.599 17.526,35.143 12.029,35.143 ; C24.2@11.673,30.988 11.684,30.999 U6.4@11.684,32.639 11.684,34.798 12.029,35.143 ; v1(12.9,40.132) 11.811,40.132 11.684,40.005 U6.2@11.684,38.989 11.684,35.488 12.029,35.143
AGND: C21.1 C22.2 SB6.2 U5.10 | length 10.9
  Top Layer w0.127: SB6.2@5.969,25.943 6.826,25.943 7.045,26.162 7.045,27.004 7.283,27.243 C21.1@8.125,27.243 C22.2@9.903,27.243 ; 6.824,25.941 7.473,25.273 10.336,25.273 11.271,24.338 U5.10@11.271,23.529
GND: B1.2 C1.1 C2.1 C3.1 C4.1 C5.2 C6.2 C7.1 C8.1 C9.1 C10.1 C11.1 C12.1 C13.1 C14.1 C15.1 C16.1 C17.1 C18.1 C19.2 C20.2 C23.1 C24.1 C25.1 C26.2 C27.1 C28.2 CN1.5 CN1.6 CN1.7 CN1.8 CN1.9 CN1.10 CN1.11 CN2.2 CN3.4 CN4.2 LD1.1 LD2.2 Q2.2 R2.2 R4.1 R7.1 R10.1 R15.1 R18.1 R21.1 R26.2 SB2.1 SB6.1 U1.8 U1.20 U1.23 U1.35 U1.47 U2.2 U3.2 U4.2 U5.4 U6.1 U7.2 U7.EP | length 19.5
  Top Layer w0.127: C25.1@4.699,10.479 C26.2@6.604,10.479 ; U4.2@9.652,42.418 v1(9.652,43.307) ; C19.2@11.427,27.243 11.43,27.246 v1(11.43,28.067) v1@11.427,28.064 ; B1.2@11.804,2.146 B1.2@11.817,2.159 ; B1.2@12.446,2.159 B1.2@12.514,2.091 ; U5.4@13.496,18.904 14.478,18.904 14.478,18.923 14.605,19.05 v1(14.732,19.05)
  Bottom Layer w0.127: v1(4.253,23.811) 3.553,23.811 3.553,22.228 4.227,21.554 U1.23@5.021,21.554 ; v1(5.588,12.065) 6.393,12.065 7.155,11.303 7.607,11.303 C5.2@7.62,11.29 ; C9.1@6.601,42.245 6.682,42.164 6.809,42.291 7.239,42.291 7.506,42.024 8.316,42.024 8.323,42.032 8.885,42.032 9.652,42.799 v1(9.652,43.307) ; v1(8.509,16.129) 8.521,16.117 U1.8@8.521,15.054 ; U1.35@11.521,23.554 11.43,23.645 11.557,23.772 11.557,24.765 ; U1.47@13.521,17.054 14.26,17.054 14.732,17.526 v1(14.732,17.78)
  other v1: 0.508,0.508 1.778,0.508 7.874,0.508 11.049,0.508 16.764,0.508 18.034,0.508 0.508,1.651 7.874,1.651 16.383,1.778 2.54,2.159 4.191,2.159 11.049,2.54 0.508,3.048 8.509,3.048 9.779,3.048 14.351,3.302 2.54,3.81 18.034,4.318 0.508,4.445 8.509,4.445 9.779,4.445 5.969,4.699 16.129,4.699 4.191,5.461 12.319,8.001 7.493,8.255 3.81,10.287 11.43,10.414 16.256,12.192 7.747,13.208 5.588,13.843 9.779,13.97 12.319,13.97 16.256,14.732 3.556,16.764 6.731,18.034 8.001,18.034 16.256,19.812 3.556,20.193 9.271,20.32 10.414,20.32 1.778,22.352 12.7,23.114 3.556,24.765 9.525,24.765 4.445,24.892 17.526,24.892 5.969,27.686 3.556,28.067 7.239,28.829 8.255,29.718 2.286,29.972 12.446,31.369 3.556,31.623 17.399,32.512 14.732,33.782 12.446,33.909 9.017,35.052 10.795,35.814 14.732,36.195 12.446,36.322 8.382,36.83 2.286,37.592 8.382,37.592 8.382,40.005 2.286,40.132 5.207,40.259 12.319,41.529 14.859,42.291 0.508,42.799 2.286,42.799 16.637,43.434 18.034,44.069 0.508,44.831 2.286,44.831 5.207,44.831 16.637,45.212 18.034,45.212 0.508,47.625 4.191,49.657 6.35,49.657 8.509,49.657 10.668,49.657 12.827,49.657
LED_STLINK: R11.1 R12.1 U1.30 | length 30.2
  Signal Layer 1 w0.127: v1(3.175,39.751) 3.175,35.306 3.95,34.531 3.95,24.801 4.712,24.039 6.005,22.746 7.861,22.746 v1(8.509,22.098)
  Signal Layer 2 w0.127: v1@3.154,39.73 v1(3.175,39.751)
  Bottom Layer w0.127: R12.1@1.27,45.655 R12.1@1.282,45.655 R11.1@2.794,45.655 2.794,40.132 v1(3.175,39.751) ; v1(8.509,22.098) 9.017,22.606 9.017,23.55 U1.30@9.021,23.554
NetC11_2: C11.2 C12.2 D2.2 D3.2 U3.1 U3.3 | length 12.2
  Top Layer w0.127: U3.3@9.845,34.628 9.845,33.716 9.906,33.655 11.684,33.655 11.745,33.716 U3.1@11.745,34.628 ; C11.2@13.208,32.512 C12.2@13.208,34.671 13.2,34.663 11.745,34.663 D2.2@11.745,37.284 D3.2@13.97,37.284
NetC13_2: C13.2 U3.4 | length 2.3
  Top Layer w0.127: C13.2@7.874,33.209 8.574,33.209 9.355,32.428 U3.4@9.845,32.428
NetC17_2: C17.2 U5.5 | length 12.8
  Top Layer w0.127: U5.5@13.496,19.704 14.853,19.704 15.38,19.177 15.38,16.518 13.335,14.473 13.335,11.176 13.843,10.668 14.351,10.668 14.478,10.541 C17.2@14.478,10.098
NetC27_2: C27.2 C28.1 SB13.1 U7.4 | length 4.6
  Top Layer w0.127: U7.4@10.571,5.273 10.993,5.273 11.243,5.523 C28.1@11.684,5.523 C27.2@12.954,5.523 12.954,5.884 13.793,6.723 SB13.1@14.351,6.723
NetCN1_4: CN1.4 R18.2 | length 7.3
  Top Layer w0.127: R18.2@3.81,44.388 R18.2@3.85,44.428 ; R18.2@3.81,44.642 4.383,44.642 4.905,45.164 4.905,45.713 5.928,46.736 8.255,46.736 8.637,46.354 CN1.4@8.637,45.306
NetCN3_1: CN3.1 SB7.2 | length 32.3
  Top Layer w0.127: SB7.2@4.699,13.3 v1(4.699,14.605)
  Signal Layer 1 w0.127: CN3.1@1.651,41.402 0.47,40.221 0.47,15.502 1.367,14.605 v1(4.699,14.605)
NetCN3_2: CN3.2 SB9.2 | length 38.3
  Top Layer w0.127: v1(7.747,10.668) 7.747,11.049 8.093,11.395 SB9.2@8.763,11.395
  Signal Layer 2 w0.127: CN3.2@1.651,38.862 0.508,37.719 0.508,10.487 1.189,9.807 6.886,9.807 v1(7.747,10.668)
NetCN4_5: CN4.5 SB8.1 SB10.1 | length 14.3
  Top Layer w0.127: SB8.1@4.438,34.409 SB10.1@6.223,34.409 6.909,34.409 7.409,33.909 8.763,33.909 9.271,33.401 12.154,33.401 12.446,33.109 12.446,32.131 12.701,31.876 13.607,31.876 ; 13.607,31.877 14.209,31.877 ; 14.209,31.876 14.943,31.876 15.577,31.242 CN4.5@16.891,31.242
NetCN4_6: CN4.6 SB11.1 SB12.1 | length 16.5
  Top Layer w0.127: SB12.1@4.191,29.218 SB11.1@5.969,29.218 6.612,29.218 6.755,29.361 6.755,31.139 7.112,31.496 10.795,31.496 11.176,31.115 11.176,30.019 11.35,29.844 12.574,29.844 13.716,28.702 CN4.6@16.891,28.702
